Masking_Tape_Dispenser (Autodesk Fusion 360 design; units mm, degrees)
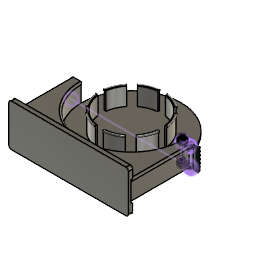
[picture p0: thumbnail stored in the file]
sketch "Tape Diameters" plane through (0, 0, 0) normal (0, 0, 1) x axis (1, 0, 0)
  circle C1 centre (0, 0) radius 37.75
  circle C2 centre (0, 0) radius 35.75
  circle C3 centre (0, 0) radius 58.5
  point P1 (0, 0)
  point P2 (0, 0)
  point P3 (0, 0)
  point P4 (0, 0)
  coincident P1 P2
  coincident P1 P3
  coincident P1 P4
  dimension "d1" diameter C1 = 75.5
  dimension "d2" diameter C2 = 71.5 (= "d1 - 4 mm")
  dimension "d3" diameter C3 = 117
extrude "Extrude1" new body sketch "Tape Diameters" profile of C1 C2 along normal blind 24
sketch "Base" plane through (0, 0, 0) normal (0, 0, 1) x axis (1, 0, 0)
  line L1 (-61, -61.5) -> (-61, 0)
  line L2 (61, -61.5) -> (-61, -61.5)
  line L3 (61, 0) -> (61, -61.5)
  line L4 (71, 0) -> (61, 0)
  line L5 (71, -71.5) -> (71, 0)
  line L6 (-71, -71.5) -> (71, -71.5)
  line L7 (-71, 0) -> (-71, -71.5)
  line L8 (-61, 0) -> (-71, 0)
  line L9 (-58.5, 0) -> (-61, 0)
  line L10 (58.5, 0) -> (61, 0)
  line L11 (71, 0) -> (-71, 0)
  circle C1 centre (0, 0) radius 58.5
  circle C2 centre (0, 0) radius 58.5
  point P12 (0, -61.5)
  point P3 (0, 0)
  point P13 (0, -71.5)
  point P7 (61, 0)
  point P4 (-61, 0)
  point P11 (-71, 0)
  point P14 (-58.5, 0)
  point P15 (58.5, 0)
  point P8 (71, 0)
  point P5 (-61, -61.5)
  point P10 (-71, -71.5)
  point P6 (61, -61.5)
  concentric C1 C2
  vertical L1
  perpendicular L1 L2
  perpendicular L2 L3
  perpendicular L3 L4
  perpendicular L4 L5
  perpendicular L5 L6
  perpendicular L6 L7
  coincident L2 P12
  vertical P3 P12
  midpoint L6 P13
  vertical P3 P13
  horizontal P3 P7
  horizontal P3 P4
  horizontal P4 P11
  coincident C2 P14
  perpendicular L1 L9
  coincident C2 P15
  perpendicular L3 L10
  dimension "d8" diameter C1 = 117
  dimension "d9" diameter C2 = 117 (= "d8")
  dimension "d10" distance P7 P8 = 10
  dimension "d11" distance P4 P11 = 10 (= "d10")
  dimension "d12" distance P5 P10 = 10 (= "d11")
  dimension "d13" distance P3 P12 = 61.5 (= "d9 / 2 + 3 mm")
  dimension "d14" distance P5 P6 = 122 (= "d9 + 5 mm")
extrude "Extrude2" new body sketch "Base" along normal blind 24
extrude "Extrude3" add sketch "Base" profile of C1 C2 L11 against normal blind 3
sketch "Lip" plane through (0, 0, 0) normal (1, 0, 0) x axis (0, 1, 0)
  line L1 (-37.75, 24) -> (37.75, 24)
  line L2 (-37.75, 3) -> (37.75, 3)
  line L3 (-37.75, 24) -> (37.75, 24)
  circle C1 centre (37.75, 24) radius 1
  point P6 (37.75, 24)
  point P8 (37.75, 24)
  coincident P6 P8
  dimension "d19" diameter C1 = 2
revolve "Revolve1" sketch "Lip" AlongAngle 360
sketch "Tape Holder Cuts" plane through (0, 0, 3) normal (0, 0, 1) x axis (-1, 0, 0)
  line L1 (4.2845, -38.5174) -> (3.9786, -35.5279)
  line L2 (-5.1589, -38.4153) -> (-5.0542, -35.3909)
  line L3 (30.2656, -24.2063) -> (27.9353, -22.3088)
  line L4 (23.5158, -30.8116) -> (21.4513, -28.599)
  line L5 (38.5174, 4.2845) -> (35.5279, 3.9786)
  line L6 (38.4153, -5.1589) -> (35.3909, -5.0542)
  line L7 (24.2063, 30.2656) -> (22.3088, 27.9353)
  line L8 (30.8116, 23.5158) -> (28.599, 21.4513)
  line L9 (-4.2845, 38.5174) -> (-3.9786, 35.5279)
  line L10 (5.1589, 38.4153) -> (5.0542, 35.3909)
  line L11 (-30.2656, 24.2063) -> (-27.9353, 22.3088)
  line L12 (-23.5158, 30.8116) -> (-21.4513, 28.599)
  line L13 (-38.5174, -4.2845) -> (-35.5279, -3.9786)
  line L14 (-38.4153, 5.1589) -> (-35.3909, 5.0542)
  line L15 (-24.2063, -30.2656) -> (-22.3088, -27.9353)
  line L16 (-30.8116, -23.5158) -> (-28.599, -21.4513)
  circle C1 centre (0, 0) radius 35.75
  circle C2 centre (0, 0) radius 36.75
  circle C3 centre (0, 0) radius 35.75
  circle C4 centre (0, 0) radius 36.75
  circle C5 centre (0, 0) radius 37.75
  arc A1 centre (0.0152, 1.0038) radius 36.7461 clockwise from (3.9786, -35.5279) to (-5.0542, -35.3909)
  arc A2 centre (-0.0375, -1.5092) radius 37.2597 clockwise from (4.2845, -38.5174) to (-5.1589, -38.4153)
  arc A3 centre (-0.699, 0.7206) radius 36.7461 clockwise from (27.9353, -22.3088) to (21.4513, -28.599)
  arc A4 centre (1.0407, -1.0937) radius 37.2597 clockwise from (30.2656, -24.2063) to (23.5158, -30.8116)
  arc A5 centre (-1.0038, 0.0152) radius 36.7461 clockwise from (35.5279, 3.9786) to (35.3909, -5.0542)
  arc A6 centre (1.5092, -0.0375) radius 37.2597 clockwise from (38.5174, 4.2845) to (38.4153, -5.1589)
  arc A7 centre (-0.7206, -0.699) radius 36.7461 clockwise from (22.3088, 27.9353) to (28.599, 21.4513)
  arc A8 centre (1.0937, 1.0407) radius 37.2597 clockwise from (24.2063, 30.2656) to (30.8116, 23.5158)
  arc A9 centre (-0.0152, -1.0038) radius 36.7461 clockwise from (-3.9786, 35.5279) to (5.0542, 35.3909)
  arc A10 centre (0.0375, 1.5092) radius 37.2597 clockwise from (-4.2845, 38.5174) to (5.1589, 38.4153)
  arc A11 centre (0.699, -0.7206) radius 36.7461 clockwise from (-27.9353, 22.3088) to (-21.4513, 28.599)
  arc A12 centre (-1.0407, 1.0937) radius 37.2597 clockwise from (-30.2656, 24.2063) to (-23.5158, 30.8116)
  arc A13 centre (1.0038, -0.0152) radius 36.7461 clockwise from (-35.5279, -3.9786) to (-35.3909, 5.0542)
  arc A14 centre (-1.5092, 0.0375) radius 37.2597 clockwise from (-38.5174, -4.2845) to (-38.4153, 5.1589)
  arc A15 centre (0.7206, 0.699) radius 36.7461 clockwise from (-22.3088, -27.9353) to (-28.599, -21.4513)
  arc A16 centre (-1.0937, -1.0407) radius 37.2597 clockwise from (-24.2063, -30.2656) to (-30.8116, -23.5158)
  point P6 (-5.0542, -35.3909)
  point P5 (3.9786, -35.5279)
  tangent C5 A1
  coincident C3 P6
  coincident C3 P5
  tangent C3 A2
  dimension "d52" C-Pattern1-Angle = 360
extrude "Extrude8" cut sketch "Tape Holder Cuts" profile of C1 C2 C3 C4 C5 A2 L1 L2 L3 A4 L4 L5 A6 L6 L7 A8 L8 L9 A10 L10 L11 A12 L12 L13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 along normal blind 27
sketch "Base (1)" plane through (0, -71.5, 0) normal (0, -1, 0) x axis (1, 0, 0)
  line L1 (71, 24) -> (71, 0)
  line L2 (-71, 24) -> (71, 24)
  line L3 (-71, 0) -> (-71, 24)
  line L4 (71, 0) -> (-71, 0)
  line L5 (71, 37) -> (-71, 37)
  line L6 (71, -13) -> (71, 37)
  line L7 (-71, -13) -> (71, -13)
  line L8 (-71, 37) -> (-71, -13)
  point P3 (71, 24)
  point P7 (71, 37)
  point P4 (-71, 24)
  point P6 (-71, 37)
  point P10 (-71, 12)
  point P11 (0, 12)
  point P12 (-71, 12)
  point P9 (-71, -13)
  horizontal L5
  vertical L6
  horizontal L7
  vertical L8
  vertical P3 P7
  vertical P4 P6
  midpoint L3 P10
  horizontal P10 P11
  midpoint L8 P12
  horizontal P11 P12
  dimension "d31" distance P6 P9 = 50
extrude "Extrude6" new body sketch "Base (1)" along normal blind 3 bodies "Foot Stand"
extrude "Extrude9" add sketch "Base (1)" profile of L2 L4 L5 L6 L7 L8 against normal blind 2
fillet "Fillet1" radius 2 2 1
fillet "Fillet2" radius 3 1
sketch "Cut Platform" plane through (0, 0, 0) normal (0, 1, 0) x axis (-1, 0, 0)
  line L1 (-58.5, 0) -> (-69, 0)
  line L2 (-58.5, 3) -> (-58.5, 0)
  line L3 (-59.4916, 3) -> (-58.5, 3)
  line L4 (-59.4916, 23.7272) -> (-59.4916, 3)
  line L5 (-69, 24) -> (-60.5, 24)
  line L6 (-71, 2) -> (-71, 22)
  line L7 (-79, 24) -> (-60.5, 24)
  line L8 (-79, 0) -> (-79, 24)
  line L9 (-60.5, 0) -> (-79, 0)
  line L10 (-60.5, 24) -> (-60.5, 0)
  line L11 (-71, 0) -> (71, 0)
  line L12 (-77, 24) -> (-79, 24)
  line L13 (-77, 0) -> (-77, 24)
  line L14 (-79, 0) -> (-77, 0)
  line L15 (-79, 24) -> (-79, 0)
  arc A1 centre (-69, 2) radius 2 clockwise from (-69, 0) to (-71, 2)
  arc A2 centre (-60.5, 22) radius 2 clockwise from (-60.5, 24) to (-59.4916, 23.7272)
  arc A3 centre (-69, 22) radius 2 clockwise from (-71, 22) to (-69, 24)
  point P9 (-60.5, 24)
  point P14 (-60.5, 24)
  point P17 (-60.5, 0)
  point P21 (-77, 0)
  point P3 (-69, 0)
  point P16 (-79, 0)
  point P15 (-79, 24)
  point P20 (-77, 24)
  horizontal L7
  vertical L8
  horizontal L9
  vertical L10
  coincident P9 P14
  coincident P17 L11
  horizontal L12
  vertical L13
  horizontal L14
  vertical L15
  coincident L9 P21
  dimension "d72" distance P3 P16 = 10
  dimension "d75" distance P15 P20 = 2
extrude "Extrude10" add sketch "Cut Platform" along normal blind 2
extrude "Extrude11" sketch "Cut Platform" profile of L7 L8 L9 L12 L13 L14 L15 blind 2
sketch "Teeth" plane through (79, 0, 0) normal (1, 0, 0) x axis (0, 1, 0)
  line L1 (0, 0) -> (0, 24)
  line L2 (4, 0) -> (0, 0)
  line L3 (4, 24) -> (4, 0)
  line L4 (0, 24) -> (4, 24)
  line L5 (4, 0) -> (2, 0)
  line L6 (4, 0) -> (4, 24)
  line L7 (2, 0) -> (2, 24)
  line L8 (2, 22) -> (4, 24)
  line L9 (2, 22) -> (4, 20)
  line L10 (4, 20) -> (4, 24)
  point P11 (2, 24)
  point P12 (2, 24)
  point P6 (2, 0)
  point P13 (2, 0)
  point P9 (4, 24)
  point P14 (4, 24)
  point P15 (2, 22)
  point P16 (4, 20)
  point P5 (4, 24)
  point P17 (4, 24)
  coincident P11 P12
  coincident P6 P13
  coincident P9 P14
  coincident L7 P15
  coincident L3 P16
  coincident P5 P17
  equal L8 L9
  dimension "d79" angle L8 L10 = 45
extrude "Extrude12" cut sketch "Teeth" profile of L3 L6 L8 L9 L10 to an object
path_pattern "PathPattern1" PathPatternDelta 20
sketch "Sharper" plane through (0, 0, 24) normal (0, 0, 1) x axis (-1, 0, 0)
  line L1 (69, 71.5) -> (69, 0)
  line L2 (-69, 71.5) -> (69, 71.5)
  line L3 (-69, 0) -> (-69, 71.5)
  line L4 (-79, 0) -> (-69, 0)
  line L5 (-79, -4) -> (-79, 0)
  line L6 (-77, -4) -> (-79, -4)
  line L7 (-77, -2) -> (-77, -4)
  line L8 (-60.5, -2) -> (-77, -2)
  line L9 (69, 0) -> (60.5, 0)
  line L10 (-77, -4) -> (-77, -2)
  line L11 (-79, -4) -> (-77, -4)
  line L12 (-78, -4) -> (-77, -2)
  line L13 (-78, -4) -> (-79, -2)
  line L14 (-60.5, 0) -> (-60.5, -2)
  arc A1 centre (0, 0) radius 60.5 clockwise from (-60.5, 0) to (60.5, 0)
  point P17 (-78, -4)
  point P9 (-77, -2)
  point P18 (-77, -2)
  point P19 (-78, -4)
  point P20 (-79, -2)
  point P21 (-78, -4)
  midpoint L11 P17
  coincident P9 P18
  coincident P17 P19
  midpoint L5 P20
  coincident P17 P21
extrude "Extrude13" cut sketch "Sharper" profile of L5 L6 L7 L10 L11 L12 L13 to an object
fillet "Fillet3" radius 2.5
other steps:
create_component "CreateComponent1"
named bodies: "Main Body", "Foot Stand"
